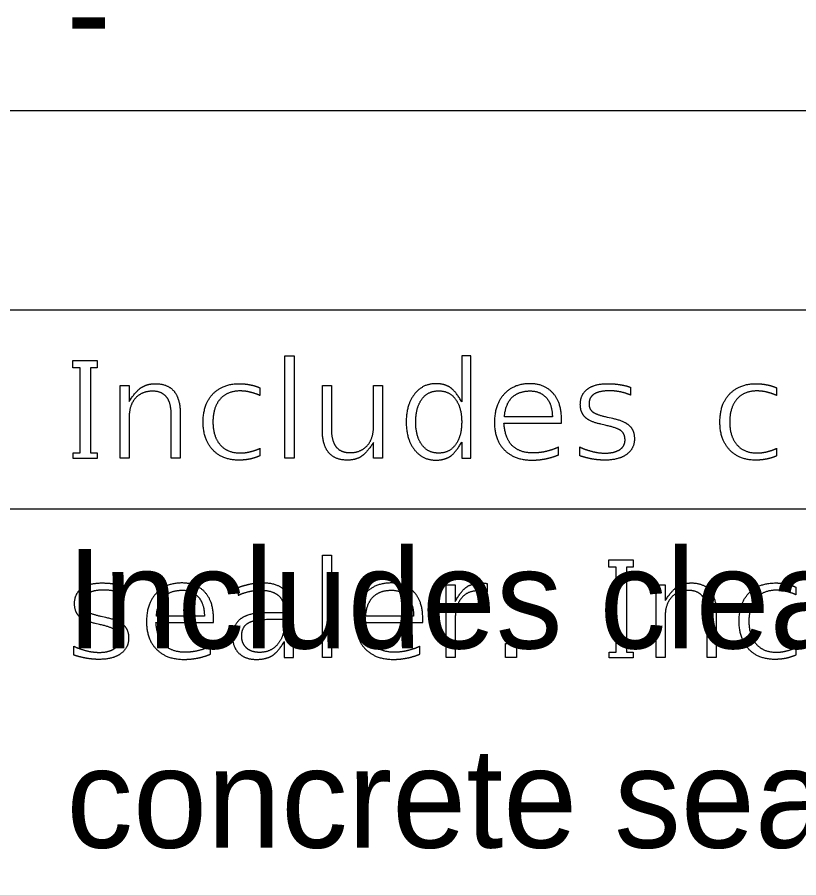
# Model space of a CAD drawing. Extents: x 0.11 to 2.72, y -0.17 to 1.89.
# Drawn here: x 1.1207 to 1.2188, y 1.0368 to 1.1447 of the extents above; entities that cross this region are included whole.
import ezdxf

# ---------------------------------------------------------------- set-up
doc = ezdxf.new("R2010")
doc.units = 0
doc.layers.add('SheetGridMinor', color=7, linetype='Continuous')
doc.layers.add('SheetText', color=7, linetype='Continuous')

msp = doc.modelspace()

# ---------------------------------------------------------------- linework, layer by layer
at = {"layer": 'SheetGridMinor'}
for p, q in [((0.15035, 1.13302), (1.94912, 1.13302)), ((0.15035, 1.10802), (1.94912, 1.10802)), ((0.15035, 1.08302), (1.94912, 1.08302))]:
    msp.add_line(p, q, dxfattribs=at)
at = {"layer": 'SheetText'}
for p, q in [((1.15114, 1.09822), (1.15114, 1.09725)), ((1.19764, 1.09829), (1.19764, 1.09731)), ((1.216, 1.09822), (1.216, 1.09725)), ((1.1707, 1.09394), (1.1707, 1.09394)), ((1.18785, 1.09459), (1.18183, 1.09458)), ((1.19471, 1.09456), (1.19525, 1.09444)), ((1.19448, 1.09353), (1.19394, 1.09366)), ((1.15114, 1.09064), (1.15114, 1.08969)), ((1.18863, 1.08981), (1.18863, 1.09079)), ((1.19129, 1.08969), (1.19129, 1.0908)), ((1.216, 1.09064), (1.216, 1.08969)), ((1.13416, 1.07329), (1.13416, 1.07231)), ((1.17966, 1.07368), (1.17967, 1.07263)), ((1.21841, 1.07322), (1.21841, 1.07225)), ((1.14842, 1.07314), (1.14842, 1.07219)), ((1.13123, 1.06956), (1.13177, 1.06944)), ((1.14418, 1.06959), (1.13815, 1.06958)), ((1.17044, 1.06959), (1.16441, 1.06958)), ((1.131, 1.06853), (1.13046, 1.06866)), ((1.12781, 1.06469), (1.12781, 1.0658)), ((1.14495, 1.06481), (1.14495, 1.06579)), ((1.17121, 1.06481), (1.17121, 1.06579)), ((1.21841, 1.06564), (1.21841, 1.06469))]:
    msp.add_line(p, q, dxfattribs=at)
for points in [[(1.12858, 1.10074), (1.12767, 1.10074), (1.12767, 1.10166), (1.13072, 1.10166), (1.13072, 1.10074), (1.12987, 1.10074), (1.12987, 1.09007), (1.13072, 1.09007), (1.13072, 1.08934), (1.12771, 1.08934), (1.12771, 1.09007), (1.12858, 1.09007)], [(1.15429, 1.10222), (1.15543, 1.10222), (1.15543, 1.0894), (1.15429, 1.0894)], [(1.159, 1.07722), (1.16014, 1.07722), (1.16014, 1.0644), (1.159, 1.0644)], [(1.19584, 1.07574), (1.19494, 1.07574), (1.19494, 1.07666), (1.19799, 1.07666), (1.19799, 1.07574), (1.19714, 1.07574), (1.19714, 1.06507), (1.19799, 1.06507), (1.19799, 1.06434), (1.19498, 1.06434), (1.19498, 1.06507), (1.19584, 1.06507)], [(1.18196, 1.06613), (1.18333, 1.06613), (1.18333, 1.0644), (1.18196, 1.0644)]]:
    msp.add_lwpolyline(points, close=True, dxfattribs=at)
for points in [[(1.17647, 1.09141), (1.17647, 1.0894), (1.17761, 1.0894), (1.17761, 1.10222), (1.17647, 1.10222), (1.17647, 1.09648)], [(1.13474, 1.09457), (1.13474, 1.0894), (1.13359, 1.0894), (1.13359, 1.09851), (1.13474, 1.09851), (1.13474, 1.09652)], [(1.15898, 1.09295), (1.15898, 1.09851), (1.16012, 1.09851), (1.16012, 1.09301)], [(1.1654, 1.09331), (1.1654, 1.09851), (1.16654, 1.09851), (1.16654, 1.0894), (1.1654, 1.0894), (1.1654, 1.09136)], [(1.14115, 1.09494), (1.14115, 1.0894), (1.14001, 1.0894), (1.14001, 1.09489)], [(1.18177, 1.09379), (1.18899, 1.09379), (1.18899, 1.09434)], [(1.17566, 1.06921), (1.17566, 1.0644), (1.17451, 1.0644), (1.17451, 1.07351), (1.17566, 1.07351), (1.17566, 1.07143)], [(1.20201, 1.06957), (1.20201, 1.0644), (1.20086, 1.0644), (1.20086, 1.07351), (1.20201, 1.07351), (1.20201, 1.07152)], [(1.15421, 1.07036), (1.15421, 1.06999), (1.1518, 1.06999)], [(1.1381, 1.06879), (1.14532, 1.06879), (1.14532, 1.06934)], [(1.15243, 1.06919), (1.15421, 1.06919), (1.15421, 1.06863)], [(1.15421, 1.06638), (1.15421, 1.0644), (1.15535, 1.0644), (1.15535, 1.06962)], [(1.16436, 1.06879), (1.17158, 1.06879), (1.17158, 1.06934)], [(1.20842, 1.06994), (1.20842, 1.0644), (1.20728, 1.0644), (1.20728, 1.06989)]]:
    msp.add_lwpolyline(points, dxfattribs=at)
for points in [[(1.13474, 1.09652), (1.13567, 1.09794), (1.13639, 1.09834)], [(1.13639, 1.09834), (1.1371, 1.09874), (1.13804, 1.09874)], [(1.13804, 1.09874), (1.13958, 1.09874), (1.14037, 1.09779)], [(1.14525, 1.09746), (1.14647, 1.09874), (1.1486, 1.09874)], [(1.1486, 1.09874), (1.1493, 1.09874), (1.14997, 1.09859)], [(1.14997, 1.09859), (1.15064, 1.09845), (1.15114, 1.09822)], [(1.1732, 1.09874), (1.17157, 1.09874), (1.17054, 1.09742)], [(1.1749, 1.09835), (1.1742, 1.09874), (1.1732, 1.09874)], [(1.17647, 1.09648), (1.17561, 1.09796), (1.1749, 1.09835)], [(1.18504, 1.09874), (1.18299, 1.09874), (1.18179, 1.09742)], [(1.18793, 1.09756), (1.18687, 1.09874), (1.18504, 1.09874)], [(1.19136, 1.09614), (1.19136, 1.09738), (1.19224, 1.09806)], [(1.19224, 1.09806), (1.19312, 1.09874), (1.19481, 1.09874)], [(1.19481, 1.09874), (1.19566, 1.09874), (1.1964, 1.09861)], [(1.1964, 1.09861), (1.19715, 1.09849), (1.19764, 1.09829)], [(1.21011, 1.09746), (1.21133, 1.09874), (1.21346, 1.09874)], [(1.21346, 1.09874), (1.21416, 1.09874), (1.21483, 1.09859)], [(1.21483, 1.09859), (1.2155, 1.09845), (1.216, 1.09822)], [(1.13769, 1.0978), (1.13633, 1.0978), (1.13553, 1.09693)], [(1.13943, 1.09706), (1.13885, 1.0978), (1.13769, 1.0978)], [(1.14001, 1.09489), (1.14001, 1.09632), (1.13943, 1.09706)], [(1.14037, 1.09779), (1.14115, 1.09684), (1.14115, 1.09494)], [(1.14402, 1.09394), (1.14402, 1.09619), (1.14525, 1.09746)], [(1.14867, 1.09783), (1.14706, 1.09783), (1.14615, 1.0968)], [(1.15007, 1.09764), (1.14938, 1.09783), (1.14867, 1.09783)], [(1.15114, 1.09725), (1.15077, 1.09745), (1.15007, 1.09764)], [(1.17054, 1.09742), (1.16951, 1.09611), (1.16951, 1.09394)], [(1.17146, 1.09679), (1.17223, 1.09785), (1.17358, 1.09785)], [(1.17358, 1.09785), (1.17493, 1.09785), (1.1757, 1.09679)], [(1.18179, 1.09742), (1.18058, 1.09611), (1.18058, 1.09386)], [(1.18183, 1.09458), (1.18197, 1.09624), (1.18282, 1.09704)], [(1.18282, 1.09704), (1.18366, 1.09783), (1.18506, 1.09783)], [(1.18506, 1.09783), (1.18631, 1.09783), (1.18707, 1.097)], [(1.18707, 1.097), (1.18784, 1.09617), (1.18785, 1.09459)], [(1.18899, 1.09434), (1.18899, 1.09639), (1.18793, 1.09756)], [(1.19311, 1.09745), (1.19245, 1.09704), (1.19245, 1.09621)], [(1.19499, 1.09785), (1.19377, 1.09785), (1.19311, 1.09745)], [(1.19653, 1.09768), (1.19579, 1.09785), (1.19499, 1.09785)], [(1.19764, 1.09731), (1.19727, 1.0975), (1.19653, 1.09768)], [(1.20888, 1.09394), (1.20888, 1.09619), (1.21011, 1.09746)], [(1.21353, 1.09783), (1.21191, 1.09783), (1.21101, 1.0968)], [(1.21493, 1.09764), (1.21424, 1.09783), (1.21353, 1.09783)], [(1.216, 1.09725), (1.21563, 1.09745), (1.21493, 1.09764)], [(1.13553, 1.09693), (1.13474, 1.09605), (1.13474, 1.09457)], [(1.14615, 1.0968), (1.14525, 1.09576), (1.14525, 1.09394)], [(1.1707, 1.09394), (1.1707, 1.09574), (1.17146, 1.09679)], [(1.1757, 1.09679), (1.17647, 1.09574), (1.17647, 1.09394)], [(1.19195, 1.09454), (1.19136, 1.09513), (1.19136, 1.09614)], [(1.19245, 1.09621), (1.19245, 1.09555), (1.19293, 1.0952)], [(1.21101, 1.0968), (1.21011, 1.09576), (1.21011, 1.09394)], [(1.19293, 1.0952), (1.1934, 1.09484), (1.19471, 1.09456)], [(1.14523, 1.09044), (1.14402, 1.09173), (1.14402, 1.09394)], [(1.14525, 1.09394), (1.14525, 1.09212), (1.14615, 1.09109)], [(1.16951, 1.09394), (1.16951, 1.09177), (1.17054, 1.09046)], [(1.17146, 1.09109), (1.1707, 1.09215), (1.1707, 1.09394)], [(1.17647, 1.09394), (1.17647, 1.09215), (1.1757, 1.09109)], [(1.18058, 1.09386), (1.18058, 1.09168), (1.18185, 1.09041)], [(1.18283, 1.09096), (1.1819, 1.09186), (1.18177, 1.09379)], [(1.19394, 1.09366), (1.19254, 1.09396), (1.19195, 1.09454)], [(1.19525, 1.09444), (1.19686, 1.09409), (1.19751, 1.09349)], [(1.21009, 1.09044), (1.20888, 1.09173), (1.20888, 1.09394)], [(1.21011, 1.09394), (1.21011, 1.09212), (1.21101, 1.09109)], [(1.15977, 1.0901), (1.15898, 1.09106), (1.15898, 1.09295)], [(1.16012, 1.09301), (1.16012, 1.09158), (1.1607, 1.09083)], [(1.1646, 1.09096), (1.1654, 1.09183), (1.1654, 1.09331)], [(1.19648, 1.09282), (1.19599, 1.09321), (1.19448, 1.09353)], [(1.19697, 1.09169), (1.19697, 1.09244), (1.19648, 1.09282)], [(1.19751, 1.09349), (1.19815, 1.09289), (1.19815, 1.09181)], [(1.1963, 1.09046), (1.19697, 1.09089), (1.19697, 1.09169)], [(1.19815, 1.09181), (1.19815, 1.0906), (1.19717, 1.08987)], [(1.14615, 1.09109), (1.14706, 1.09005), (1.14867, 1.09005)], [(1.15007, 1.09024), (1.15077, 1.09043), (1.15114, 1.09064)], [(1.1607, 1.09083), (1.16128, 1.09009), (1.16244, 1.09009)], [(1.16244, 1.09009), (1.1638, 1.09009), (1.1646, 1.09096)], [(1.1654, 1.09136), (1.16446, 1.08994), (1.16375, 1.08954)], [(1.17358, 1.09003), (1.17223, 1.09003), (1.17146, 1.09109)], [(1.1757, 1.09109), (1.17493, 1.09003), (1.17358, 1.09003)], [(1.1749, 1.08954), (1.17561, 1.08992), (1.17647, 1.09141)], [(1.18541, 1.09005), (1.18377, 1.09005), (1.18283, 1.09096)], [(1.18863, 1.09079), (1.18808, 1.09051), (1.18721, 1.09028)], [(1.19129, 1.0908), (1.19187, 1.0905), (1.19274, 1.09027)], [(1.21101, 1.09109), (1.21191, 1.09005), (1.21353, 1.09005)], [(1.21493, 1.09024), (1.21563, 1.09043), (1.216, 1.09064)], [(1.1485, 1.08915), (1.14644, 1.08915), (1.14523, 1.09044)], [(1.14867, 1.09005), (1.14938, 1.09005), (1.15007, 1.09024)], [(1.15114, 1.08969), (1.15063, 1.08945), (1.14995, 1.0893)], [(1.16211, 1.08915), (1.16057, 1.08915), (1.15977, 1.0901)], [(1.16375, 1.08954), (1.16305, 1.08915), (1.16211, 1.08915)], [(1.17054, 1.09046), (1.17157, 1.08915), (1.1732, 1.08915)], [(1.1732, 1.08915), (1.1742, 1.08915), (1.1749, 1.08954)], [(1.18185, 1.09041), (1.18312, 1.08915), (1.18532, 1.08915)], [(1.18721, 1.09028), (1.18634, 1.09005), (1.18541, 1.09005)], [(1.18707, 1.08933), (1.18793, 1.08952), (1.18863, 1.08981)], [(1.19286, 1.08929), (1.19205, 1.08944), (1.19129, 1.08969)], [(1.19274, 1.09027), (1.19361, 1.09003), (1.19446, 1.09003)], [(1.19717, 1.08987), (1.1962, 1.08915), (1.19442, 1.08915)], [(1.19446, 1.09003), (1.19562, 1.09003), (1.1963, 1.09046)], [(1.21336, 1.08915), (1.2113, 1.08915), (1.21009, 1.09044)], [(1.21353, 1.09005), (1.21424, 1.09005), (1.21493, 1.09024)], [(1.216, 1.08969), (1.21549, 1.08945), (1.21481, 1.0893)], [(1.14995, 1.0893), (1.14927, 1.08915), (1.1485, 1.08915)], [(1.18532, 1.08915), (1.1862, 1.08915), (1.18707, 1.08933)], [(1.19442, 1.08915), (1.19368, 1.08915), (1.19286, 1.08929)], [(1.21481, 1.0893), (1.21413, 1.08915), (1.21336, 1.08915)], [(1.12876, 1.07306), (1.12964, 1.07374), (1.13133, 1.07374)], [(1.13133, 1.07374), (1.13218, 1.07374), (1.13292, 1.07361)], [(1.13292, 1.07361), (1.13367, 1.07349), (1.13416, 1.07329)], [(1.14137, 1.07374), (1.13932, 1.07374), (1.13811, 1.07242)], [(1.14426, 1.07256), (1.1432, 1.07374), (1.14137, 1.07374)], [(1.14991, 1.07357), (1.14912, 1.07341), (1.14842, 1.07314)], [(1.15145, 1.07374), (1.15071, 1.07374), (1.14991, 1.07357)], [(1.15438, 1.07273), (1.15342, 1.07374), (1.15145, 1.07374)], [(1.16763, 1.07374), (1.16558, 1.07374), (1.16437, 1.07242)], [(1.17052, 1.07256), (1.16946, 1.07374), (1.16763, 1.07374)], [(1.17566, 1.07143), (1.17652, 1.07294), (1.17726, 1.07334)], [(1.17726, 1.07334), (1.178, 1.07374), (1.17908, 1.07374)], [(1.17908, 1.07374), (1.17924, 1.07374), (1.17942, 1.07371)], [(1.17942, 1.07371), (1.1796, 1.07369), (1.17966, 1.07368)], [(1.20201, 1.07152), (1.20294, 1.07294), (1.20365, 1.07334)], [(1.20365, 1.07334), (1.20437, 1.07374), (1.20531, 1.07374)], [(1.20531, 1.07374), (1.20685, 1.07374), (1.20763, 1.07279)], [(1.21251, 1.07246), (1.21374, 1.07374), (1.21587, 1.07374)], [(1.21587, 1.07374), (1.21657, 1.07374), (1.21724, 1.07359)], [(1.21724, 1.07359), (1.21791, 1.07345), (1.21841, 1.07322)], [(1.12788, 1.07114), (1.12788, 1.07238), (1.12876, 1.07306)], [(1.12963, 1.07245), (1.12897, 1.07204), (1.12897, 1.07121)], [(1.13151, 1.07285), (1.13029, 1.07285), (1.12963, 1.07245)], [(1.13305, 1.07268), (1.1323, 1.07285), (1.13151, 1.07285)], [(1.13416, 1.07231), (1.13379, 1.0725), (1.13305, 1.07268)], [(1.13811, 1.07242), (1.13691, 1.07111), (1.13691, 1.06886)], [(1.13914, 1.07204), (1.13999, 1.07283), (1.14139, 1.07283)], [(1.14139, 1.07283), (1.14264, 1.07283), (1.1434, 1.072)], [(1.14532, 1.06934), (1.14532, 1.07139), (1.14426, 1.07256)], [(1.14842, 1.07219), (1.14884, 1.07242), (1.14964, 1.07263)], [(1.14964, 1.07263), (1.15044, 1.07283), (1.15128, 1.07283)], [(1.15128, 1.07283), (1.15265, 1.07283), (1.15343, 1.07219)], [(1.15343, 1.07219), (1.15421, 1.07154), (1.15421, 1.07036)], [(1.15535, 1.06962), (1.15535, 1.07172), (1.15438, 1.07273)], [(1.16437, 1.07242), (1.16317, 1.07111), (1.16317, 1.06886)], [(1.1654, 1.07204), (1.16625, 1.07283), (1.16764, 1.07283)], [(1.16764, 1.07283), (1.1689, 1.07283), (1.16966, 1.072)], [(1.17158, 1.06934), (1.17158, 1.07139), (1.17052, 1.07256)], [(1.17863, 1.07277), (1.17719, 1.07277), (1.17643, 1.07183)], [(1.17937, 1.07269), (1.17903, 1.07277), (1.17863, 1.07277)], [(1.17966, 1.07262), (1.17962, 1.07262), (1.17937, 1.07269)], [(1.17967, 1.07263), (1.17967, 1.07262), (1.17966, 1.07262)], [(1.20496, 1.0728), (1.20359, 1.0728), (1.2028, 1.07193)], [(1.2067, 1.07206), (1.20611, 1.0728), (1.20496, 1.0728)], [(1.20763, 1.07279), (1.20842, 1.07184), (1.20842, 1.06994)], [(1.21129, 1.06894), (1.21129, 1.07119), (1.21251, 1.07246)], [(1.21594, 1.07283), (1.21432, 1.07283), (1.21342, 1.0718)], [(1.21734, 1.07264), (1.21665, 1.07283), (1.21594, 1.07283)], [(1.21841, 1.07225), (1.21804, 1.07245), (1.21734, 1.07264)], [(1.12847, 1.06954), (1.12788, 1.07013), (1.12788, 1.07114)], [(1.12897, 1.07121), (1.12897, 1.07055), (1.12944, 1.0702)], [(1.13815, 1.06958), (1.13829, 1.07124), (1.13914, 1.07204)], [(1.1434, 1.072), (1.14416, 1.07117), (1.14418, 1.06959)], [(1.16441, 1.06958), (1.16455, 1.07124), (1.1654, 1.07204)], [(1.16966, 1.072), (1.17042, 1.07117), (1.17044, 1.06959)], [(1.17643, 1.07183), (1.17566, 1.0709), (1.17566, 1.06921)], [(1.2028, 1.07193), (1.20201, 1.07105), (1.20201, 1.06957)], [(1.20728, 1.06989), (1.20728, 1.07132), (1.2067, 1.07206)], [(1.21342, 1.0718), (1.21252, 1.07076), (1.21252, 1.06894)], [(1.12944, 1.0702), (1.12992, 1.06984), (1.13123, 1.06956)], [(1.1518, 1.06999), (1.14973, 1.06999), (1.14872, 1.06923)], [(1.13046, 1.06866), (1.12906, 1.06896), (1.12847, 1.06954)], [(1.13177, 1.06944), (1.13338, 1.06909), (1.13402, 1.06849)], [(1.14872, 1.06923), (1.14772, 1.06847), (1.14772, 1.06696)], [(1.14967, 1.06871), (1.15048, 1.06919), (1.15243, 1.06919)], [(1.2125, 1.06544), (1.21129, 1.06673), (1.21129, 1.06894)], [(1.21252, 1.06894), (1.21252, 1.06712), (1.21342, 1.06609)], [(1.133, 1.06782), (1.13251, 1.06821), (1.131, 1.06853)], [(1.13349, 1.06669), (1.13349, 1.06744), (1.133, 1.06782)], [(1.13402, 1.06849), (1.13467, 1.06789), (1.13467, 1.06681)], [(1.13691, 1.06886), (1.13691, 1.06668), (1.13818, 1.06541)], [(1.13916, 1.06596), (1.13823, 1.06686), (1.1381, 1.06879)], [(1.14886, 1.06706), (1.14886, 1.06823), (1.14967, 1.06871)], [(1.15421, 1.06863), (1.15421, 1.06702), (1.15336, 1.06603)], [(1.16317, 1.06886), (1.16317, 1.06668), (1.16443, 1.06541)], [(1.16542, 1.06596), (1.16449, 1.06686), (1.16436, 1.06879)], [(1.13467, 1.06681), (1.13467, 1.0656), (1.13369, 1.06487)], [(1.14772, 1.06696), (1.14772, 1.06567), (1.14852, 1.06491)], [(1.14947, 1.06558), (1.14886, 1.06613), (1.14886, 1.06706)], [(1.12781, 1.0658), (1.12839, 1.0655), (1.12926, 1.06527)], [(1.13282, 1.06546), (1.13349, 1.06589), (1.13349, 1.06669)], [(1.14173, 1.06505), (1.14009, 1.06505), (1.13916, 1.06596)], [(1.14495, 1.06579), (1.14441, 1.06551), (1.14353, 1.06528)], [(1.15336, 1.06603), (1.15252, 1.06503), (1.15111, 1.06503)], [(1.15255, 1.06454), (1.1533, 1.06492), (1.15421, 1.06638)], [(1.16799, 1.06505), (1.16635, 1.06505), (1.16542, 1.06596)], [(1.17121, 1.06579), (1.17067, 1.06551), (1.16979, 1.06528)], [(1.21342, 1.06609), (1.21432, 1.06505), (1.21594, 1.06505)], [(1.12938, 1.06429), (1.12857, 1.06444), (1.12781, 1.06469)], [(1.12926, 1.06527), (1.13013, 1.06503), (1.13098, 1.06503)], [(1.13369, 1.06487), (1.13271, 1.06415), (1.13094, 1.06415)], [(1.13098, 1.06503), (1.13214, 1.06503), (1.13282, 1.06546)], [(1.13818, 1.06541), (1.13944, 1.06415), (1.14164, 1.06415)], [(1.14353, 1.06528), (1.14266, 1.06505), (1.14173, 1.06505)], [(1.14339, 1.06433), (1.14425, 1.06451), (1.14495, 1.06481)], [(1.14852, 1.06491), (1.14932, 1.06415), (1.1507, 1.06415)], [(1.15111, 1.06503), (1.15008, 1.06503), (1.14947, 1.06558)], [(1.16443, 1.06541), (1.1657, 1.06415), (1.1679, 1.06415)], [(1.16979, 1.06528), (1.16892, 1.06505), (1.16799, 1.06505)], [(1.16965, 1.06433), (1.17051, 1.06451), (1.17121, 1.06481)], [(1.21577, 1.06415), (1.21371, 1.06415), (1.2125, 1.06544)], [(1.21594, 1.06505), (1.21665, 1.06505), (1.21734, 1.06524)], [(1.21841, 1.06469), (1.2179, 1.06445), (1.21722, 1.0643)], [(1.21734, 1.06524), (1.21804, 1.06543), (1.21841, 1.06564)], [(1.13094, 1.06415), (1.13019, 1.06415), (1.12938, 1.06429)], [(1.14164, 1.06415), (1.14253, 1.06415), (1.14339, 1.06433)], [(1.1507, 1.06415), (1.1518, 1.06415), (1.15255, 1.06454)], [(1.1679, 1.06415), (1.16878, 1.06415), (1.16965, 1.06433)], [(1.21722, 1.0643), (1.21654, 1.06415), (1.21577, 1.06415)]]:
    msp.add_open_spline(points, degree=2, dxfattribs=at)

# ---------------------------------------------------------------- texts
for s, p in [('-', (1.12686, 1.13918)), ('Includes cleaning existing concrete rails and curbs and furnishing and placing', (1.12686, 1.06552)), ('concrete sealer. Includes CF Joint replacement at end of deck.', (1.12686, 1.04052))]:
    msp.add_text(s, height=0.0125, dxfattribs=at).set_placement(p)

doc.saveas('drawing.dxf')
